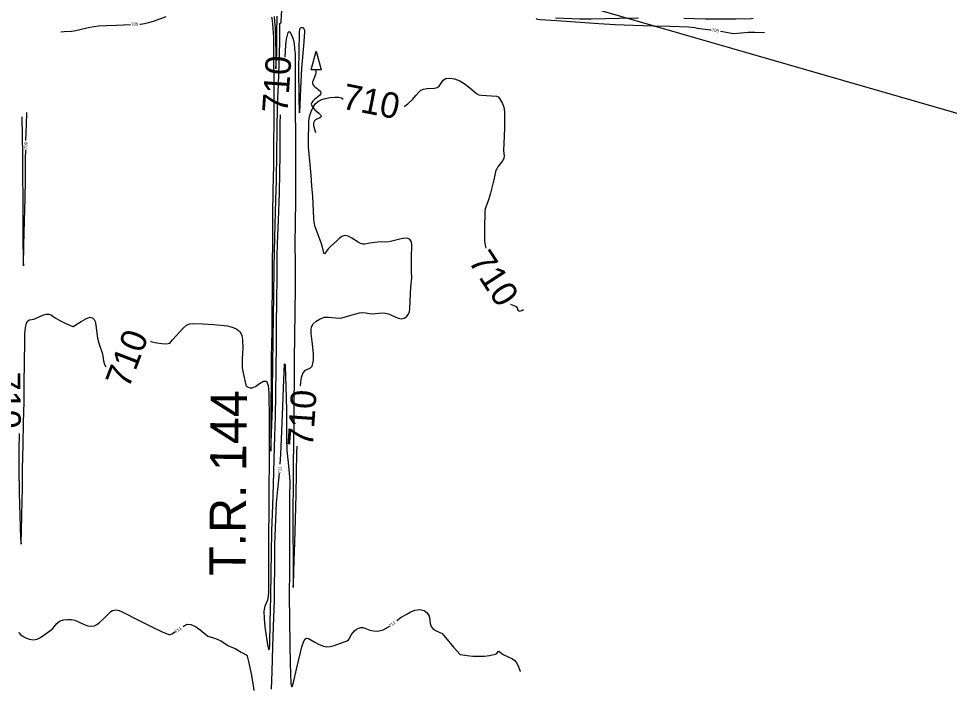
# Model space of a CAD drawing. Extents: x -468548933 to 3387700, y -306089263 to 1207014.
# Drawn here: x 1840205 to 1841407, y 537981 to 538847 of the extents above; entities that cross this region are included whole.
import ezdxf

# ---------------------------------------------------------------- set-up
doc = ezdxf.new("R2010")
doc.units = 0
for name, color, linetype in [('DT_X_Contour_Minor', 7, 'Continuous'), ('Level 19', 7, 'Continuous'), ('Level 40', 7, 'Continuous'), ('Level 56', 7, 'Continuous'), ('SC_Scratch1', 7, 'Continuous')]:
    doc.layers.add(name, color=color, linetype=linetype)

msp = doc.modelspace()

# ---------------------------------------------------------------- linework, layer by layer
at = {"layer": 'DT_X_Contour_Minor'}
for points in [[(1840531.6, 538848.3), (1840532.3, 538844), (1840533.8, 538828.8), (1840533.9, 538822.2), (1840534.2, 538796.9), (1840534.6, 538764.8), (1840534.4, 538739.9), (1840534.4, 538715.2), (1840534.3, 538684.4), (1840533.9, 538656.8), (1840533.4, 538624.7), (1840532.9, 538593), (1840532.7, 538561.2), (1840532.5, 538527.4), (1840532.3, 538498.9), (1840532.1, 538467.3), (1840531.8, 538443.1), (1840531.3, 538408.7), (1840531, 538379.9), (1840530.8, 538347.1), (1840530.6, 538318.7), (1840530.5, 538287.6), (1840530.7, 538287.8), (1840531.4, 538310.8), (1840532.6, 538344.6), (1840533, 538365.7), (1840533.3, 538399.8), (1840533.6, 538431.1), (1840534.1, 538462), (1840534.4, 538489.5), (1840534.8, 538523.6), (1840535.2, 538546.4), (1840536.3, 538580.4), (1840537.3, 538612.4), (1840537.8, 538637.3), (1840538.5, 538673), (1840538.8, 538702.3), (1840539.3, 538733.9), (1840540.4, 538761.8), (1840541.6, 538787.5), (1840542.1, 538816.1), (1840542.5, 538840.4), (1840542.7, 538840.6), (1840543.3, 538840.3), (1840543.6, 538840.7), (1840543.8, 538842.7), (1840544.8, 538857.5)], [(1840361.5, 538839.6), (1840362.4, 538839.6), (1840367.3, 538840.1), (1840373.1, 538841.5), (1840380.5, 538843.9), (1840395.3, 538849.2)], [(1840534.8, 538849.3), (1840535.6, 538843), (1840536.1, 538834.3), (1840537.1, 538802.1), (1840537.2, 538791.4), (1840537.2, 538781.6), (1840537.7, 538788.5), (1840538.2, 538800.9), (1840538.5, 538827.1), (1840538.9, 538849.6)], [(1840873.5, 538847), (1840873.8, 538846.3), (1840875.4, 538845.8), (1840878.2, 538845.4), (1840900, 538844.2), (1840930.5, 538842), (1840954.5, 538840.2), (1840975.5, 538838.8), (1840998.8, 538838), (1841024.8, 538837.3), (1841046.5, 538836.7), (1841070.1, 538835.8), (1841078.6, 538835.1), (1841081.3, 538834.1), (1841098.8, 538832.3), (1841099.6, 538832.2)], [(1841005.7, 538847), (1840981, 538846.6), (1840944.8, 538845.9), (1840929.9, 538846.1), (1840898.3, 538847.1)], [(1841153.8, 538846.6), (1841151.2, 538846.2), (1841131.6, 538846), (1841091.7, 538846), (1841064.1, 538846.6)], [(1840259.2, 538829.7), (1840263.7, 538829.9), (1840273.1, 538830.3), (1840276.6, 538830.8), (1840296.6, 538835.4), (1840307.9, 538837.1), (1840317.9, 538837.7), (1840331.2, 538838.1), (1840349.5, 538839.1)], [(1840549.2, 538796.8), (1840550.2, 538812.7), (1840551, 538819.9), (1840552, 538825.3), (1840553.1, 538828.6), (1840554.3, 538830), (1840555.4, 538829.3), (1840556.5, 538827.5), (1840559.1, 538821.3), (1840559.9, 538818.4), (1840560.6, 538814), (1840561.4, 538808.2), (1840561.9, 538801.1), (1840562.3, 538784.6), (1840562.3, 538762), (1840562.2, 538727.7), (1840562.4, 538696.9), (1840562.7, 538666.4), (1840562.7, 538640.5), (1840562.4, 538611.8), (1840561.9, 538582.4), (1840561.8, 538556.2), (1840562, 538530), (1840562, 538496.5), (1840561.6, 538468.7), (1840561.1, 538435.3), (1840560.9, 538407.4), (1840560.7, 538378.4), (1840560.5, 538353.6), (1840560.2, 538325), (1840559.9, 538298.8), (1840559.6, 538269.1), (1840559.4, 538242), (1840559, 538213.6), (1840559.2, 538185), (1840559.5, 538148.6), (1840559.4, 538117.3), (1840559.5, 538111.8), (1840559.8, 538116.2), (1840560.9, 538146.8), (1840561.5, 538169.6), (1840562.4, 538199.6), (1840563.4, 538231.8), (1840563.9, 538259.3), (1840564.2, 538286.2), (1840564.5, 538294.4)], [(1840567.6, 538828.2), (1840568.2, 538833.2), (1840568.6, 538834.2), (1840569.2, 538834.7), (1840570, 538835), (1840571.2, 538835), (1840572.5, 538834.6), (1840573.5, 538833.6), (1840574, 538831.8), (1840574, 538829), (1840572.9, 538811.6), (1840570.3, 538782.4), (1840569.2, 538755.7), (1840567.5, 538724.9), (1840567.3, 538746.1), (1840566.9, 538780.7), (1840567.2, 538804.3), (1840567.6, 538828.2)], [(1841111.5, 538830.5), (1841116.7, 538829.7), (1841125.8, 538827.6), (1841129.2, 538827.3), (1841147.4, 538829.2), (1841156, 538829.3), (1841168.6, 538828.8)], [(1840703, 538732.9), (1840707.8, 538736.7), (1840713.6, 538742.2), (1840718.6, 538747.6), (1840722, 538751.5), (1840724.6, 538754.1), (1840727.7, 538755.6), (1840732.2, 538756.1), (1840742.1, 538756.7), (1840745.6, 538757.8), (1840748, 538759.5), (1840749.7, 538761.8), (1840751.4, 538764.5), (1840753.5, 538767.2), (1840756.8, 538769.1), (1840761.8, 538769.7), (1840768.1, 538768.9), (1840774.9, 538766.3), (1840781.6, 538762), (1840787.8, 538757.1), (1840796.2, 538749.8), (1840799.2, 538748.3), (1840803, 538747.6), (1840822.4, 538746.5), (1840824.3, 538745.4), (1840825.9, 538743.5), (1840829.8, 538737.1), (1840831.4, 538733.6), (1840832.2, 538730.4), (1840832.5, 538725), (1840832.6, 538706.1), (1840832.3, 538694.6), (1840831.1, 538676.4), (1840832.1, 538669.1), (1840831.9, 538666.1), (1840830.4, 538663.2), (1840823.9, 538655), (1840822.5, 538652.7), (1840821.5, 538650.6), (1840820.7, 538646.5), (1840818.7, 538638.2), (1840814.4, 538621.2), (1840812, 538612.4), (1840807.7, 538600.8), (1840807.2, 538597.7), (1840806.6, 538574.8), (1840806.6, 538563.2), (1840806.8, 538558.5), (1840808, 538551.8), (1840808.3, 538550.1)], [(1840569.1, 538372.3), (1840569.3, 538376.4), (1840570.4, 538383.5), (1840572.5, 538389.1), (1840575.5, 538392.2), (1840582.1, 538395.4), (1840584, 538397.7), (1840585.1, 538400.9), (1840585.6, 538404.7), (1840585.7, 538408.8), (1840585.6, 538413.5), (1840584.4, 538426.2), (1840582.8, 538439.9), (1840582.6, 538444.8), (1840583.3, 538448.6), (1840585.4, 538452.1), (1840589.2, 538455.6), (1840594.2, 538458.7), (1840599.8, 538460.7), (1840605.4, 538461.1), (1840618.9, 538459.7), (1840622.2, 538460.2), (1840632.6, 538462.9), (1840645.3, 538466.4), (1840649.6, 538466.9), (1840653.6, 538466.5), (1840657.6, 538465.7), (1840661.6, 538465.3), (1840665.9, 538465.6), (1840670.3, 538466.2), (1840674.6, 538466.6), (1840678.6, 538466.1), (1840682.6, 538465), (1840695.2, 538459.4), (1840699.4, 538458.8), (1840703.2, 538459.8), (1840706.4, 538462), (1840708.7, 538464.9), (1840709.9, 538468.2), (1840710.4, 538471.6), (1840711.3, 538491.1), (1840711.6, 538499.7), (1840712.8, 538511.9), (1840712.6, 538520.5), (1840712.2, 538529), (1840712.2, 538537.2), (1840712.8, 538554.2), (1840712.3, 538558), (1840710.8, 538560.9), (1840708, 538562.5), (1840704, 538562.9), (1840699.1, 538562.3), (1840683.6, 538558.2), (1840679.9, 538557.8), (1840673, 538558), (1840668.3, 538557.8), (1840658.4, 538556.4), (1840652, 538555.1), (1840649.5, 538555.3), (1840646.6, 538556.2), (1840643.3, 538557.9), (1840635.1, 538563.1), (1840630.5, 538565.4), (1840626.1, 538566.3), (1840622.4, 538565.1), (1840619, 538562.5), (1840615.6, 538559.2), (1840608.2, 538552.8), (1840605.1, 538549.7), (1840600.2, 538542.8), (1840599.3, 538543.7), (1840598.5, 538545.8), (1840597, 538553), (1840595.7, 538557), (1840590.4, 538570.6), (1840588, 538577.7), (1840586.6, 538583.6), (1840586.1, 538588.9), (1840585, 538616.6), (1840583.7, 538630.4), (1840582.6, 538643.7), (1840580.2, 538671.9), (1840579.3, 538679.9), (1840579.3, 538687.5), (1840579.8, 538713.6), (1840580.1, 538717.4), (1840581.1, 538721.3), (1840582.8, 538726.5), (1840585.3, 538732), (1840588.4, 538736.8), (1840592.1, 538740.1), (1840596.4, 538742.1), (1840601.5, 538743.4), (1840607.5, 538744.5), (1840613.5, 538745.1), (1840618.5, 538745.1), (1840621.8, 538744.1), (1840624.2, 538742.7)], [(1840214.2, 538689.1), (1840214.9, 538709.9), (1840215.3, 538725.5)], [(1840375.3, 538429.7), (1840377.1, 538429), (1840383.5, 538427.6), (1840389.9, 538426.8), (1840395.1, 538426.5), (1840398.2, 538426.7), (1840400, 538427.4), (1840404, 538431.9), (1840416.8, 538446.1), (1840421.6, 538450.4), (1840424.6, 538452), (1840425.9, 538452.3), (1840430.9, 538452.5), (1840442.6, 538452.1), (1840457, 538451.3), (1840474.5, 538449.6), (1840477.6, 538448.9), (1840482, 538447.6), (1840486.9, 538445.3), (1840490.9, 538441.9), (1840493.2, 538437.2), (1840494, 538432), (1840494.3, 538420.7), (1840493.8, 538407), (1840493.6, 538398.5), (1840493.8, 538395.3), (1840495.3, 538387), (1840498.2, 538372.9), (1840498.8, 538372.2), (1840499.7, 538371.5), (1840501.2, 538370.6), (1840503.4, 538369.8), (1840506.6, 538369.6), (1840510.8, 538371.3), (1840515.9, 538375), (1840521.1, 538378.3), (1840525.2, 538378.3), (1840527.4, 538372.8), (1840528.2, 538363.1), (1840528.4, 538329.6), (1840528.4, 538302.7), (1840528.4, 538272), (1840528.2, 538241.5), (1840527.9, 538210.6), (1840527.7, 538178.6), (1840527.7, 538148.6), (1840527.8, 538121.6), (1840527.7, 538105.5), (1840527.3, 538099.8), (1840526.3, 538095.4), (1840522.7, 538087.5), (1840521.7, 538081), (1840522, 538071.4), (1840523.1, 538060.8), (1840526.4, 538037.5), (1840527.8, 538032.1), (1840528.5, 538031.1), (1840529, 538032.9), (1840529.3, 538037.7), (1840530, 538067.4), (1840530.8, 538099.6), (1840531.3, 538131.1), (1840531.5, 538155.5), (1840532, 538184.9), (1840533.1, 538217.7), (1840534.1, 538244.5), (1840535, 538277.9), (1840535.7, 538306.6), (1840536.5, 538332.6), (1840537.1, 538360.7), (1840537.5, 538394.5), (1840537.8, 538423.3), (1840538.1, 538449.1), (1840538.5, 538484.1), (1840538.7, 538510.8), (1840538.9, 538539.2), (1840539.3, 538556.3), (1840540.4, 538586.2), (1840541.7, 538621.5), (1840542.4, 538647.5), (1840542.6, 538671.1), (1840542.9, 538711.1), (1840543.2, 538722.5)], [(1840208.9, 538719.5), (1840209, 538717.9), (1840209.4, 538696.2), (1840209.7, 538670), (1840209.9, 538643.5), (1840210.3, 538614.2), (1840210.3, 538584.4), (1840210.3, 538565.3), (1840210.7, 538532.8), (1840210.9, 538527.2), (1840211.7, 538554.1), (1840212.4, 538584.9), (1840213.2, 538615), (1840213.6, 538637.9), (1840213.8, 538665.4), (1840214, 538677.1)], [(1840840.2, 538477.6), (1840846.6, 538475), (1840848.1, 538474.1), (1840848.8, 538472.8), (1840849.4, 538471), (1840850.3, 538469.3), (1840852, 538468.6), (1840854.8, 538469.6), (1840857.1, 538470.8)], [(1840205.3, 538310.5), (1840205.1, 538290), (1840204.9, 538266), (1840205.4, 538233.6), (1840206.2, 538204.4), (1840207.1, 538174.9), (1840207.9, 538167.5), (1840208.2, 538169.5), (1840208.7, 538185.2), (1840209.1, 538205.6), (1840209.7, 538240.3), (1840210, 538264.6), (1840210.6, 538296.3), (1840211.3, 538324.7), (1840211.9, 538351.7), (1840212, 538375.5), (1840212.3, 538402), (1840212.7, 538429.8), (1840213, 538439.2), (1840213.6, 538447.2), (1840214.8, 538453.1), (1840216.7, 538456.3), (1840218.9, 538457.5), (1840224.6, 538458.3), (1840231.3, 538461.3), (1840235.9, 538463.3), (1840240.4, 538464.6), (1840244.2, 538464.6), (1840247.2, 538463.5), (1840252.2, 538460.2), (1840258.1, 538456.5), (1840266, 538452.5), (1840274.8, 538448.7), (1840275.3, 538448.7), (1840277.6, 538450.1), (1840285.8, 538455.5), (1840291.7, 538458.8), (1840296.9, 538460.7), (1840300.4, 538460.2), (1840302.5, 538457.9), (1840303.5, 538455.3), (1840304.5, 538450.7), (1840306.9, 538433.9), (1840308.3, 538427.2), (1840310.5, 538421), (1840311.9, 538417.4), (1840313, 538413.4), (1840314.5, 538404.5), (1840315.9, 538399.8), (1840317.4, 538396.8)], [(1840542.7, 538271.1), (1840543.5, 538283.8), (1840545, 538313.7), (1840546, 538345.5), (1840547, 538369.4), (1840548.5, 538400.2), (1840548.7, 538400.5), (1840549, 538399.3), (1840549.2, 538397.2), (1840550, 538371.6), (1840551.1, 538340.1), (1840550.9, 538319.4), (1840550.7, 538303.7), (1840551.4, 538288.7), (1840552.9, 538273.1), (1840554.8, 538254.5), (1840555, 538248.3), (1840554.9, 538228.8), (1840554.9, 538191.8), (1840554.8, 538165.1), (1840554.7, 538134.1), (1840554.5, 538101.3), (1840554.8, 538069.9), (1840555.3, 538037.8), (1840555.8, 538013.4), (1840556.7, 537987.6), (1840557.2, 537983.7), (1840557.7, 537983.3), (1840558.5, 537984.4), (1840560, 537988.9), (1840564, 538006.3), (1840568.9, 538027.8), (1840570.9, 538035), (1840572.9, 538040.9), (1840574.8, 538044.9), (1840576.8, 538046.3), (1840579.2, 538045.7), (1840587.5, 538040.8), (1840593.1, 538038), (1840598.5, 538035.9), (1840603.1, 538035), (1840607.2, 538035.3), (1840611.2, 538036.3), (1840626.9, 538041.9), (1840629.3, 538042.8), (1840631, 538044), (1840632.3, 538045.7), (1840634.6, 538050.3), (1840636.5, 538053), (1840638.8, 538055.5), (1840641.4, 538057.7), (1840644.2, 538059.2), (1840647, 538060), (1840649.6, 538060), (1840652.1, 538059.3), (1840658.5, 538056.7), (1840663.3, 538055.6), (1840669.1, 538055.4), (1840675.7, 538057), (1840682.6, 538060.7), (1840684, 538061.7)], [(1840531.4, 537980.3), (1840532.3, 538003), (1840533.4, 538035.1), (1840534.2, 538061.2), (1840535.3, 538095.3), (1840535.6, 538108.8), (1840535.7, 538141.6), (1840535.9, 538167.1), (1840537.1, 538199.4), (1840538.1, 538220.9), (1840539.8, 538238.1), (1840541.7, 538259.1)], [(1840204.6, 538053.7), (1840205.5, 538053), (1840206.8, 538051.5), (1840209.3, 538049.4), (1840213.4, 538046.9), (1840218.6, 538044.8), (1840223.9, 538043.9), (1840228.7, 538044.8), (1840233.1, 538047), (1840245.3, 538055.6), (1840248.8, 538058.7), (1840254.3, 538065.3), (1840257.8, 538068), (1840262.6, 538069.7), (1840268, 538070.5), (1840273.2, 538070.4), (1840277.5, 538069.4), (1840281.2, 538067.8), (1840289.6, 538063.9), (1840294.3, 538062.3), (1840298.8, 538061.6), (1840302.7, 538062.2), (1840306, 538063.9), (1840309.1, 538066.3), (1840314.8, 538071.7), (1840324.1, 538080.8), (1840325.9, 538081.8), (1840328.2, 538082.5), (1840331.1, 538082.7), (1840334.6, 538082), (1840338.7, 538080.3), (1840359.8, 538069.4), (1840375, 538061.5), (1840390.2, 538054.5), (1840398.7, 538050.9), (1840400.5, 538050.8), (1840402.6, 538051.8), (1840407.3, 538054.6)], [(1840693.5, 538068.9), (1840699, 538073.3), (1840705.5, 538076.9), (1840710.6, 538079.6), (1840716.9, 538082.2), (1840723.3, 538083.3), (1840728.7, 538082.1), (1840732.8, 538078.9), (1840735.2, 538074.5), (1840736.1, 538069.8), (1840736.5, 538065.2), (1840737.7, 538061.1), (1840740.6, 538058), (1840744.3, 538055.7), (1840752, 538052), (1840754, 538049.6), (1840766.7, 538034.6), (1840775.2, 538025), (1840784.5, 538023.8), (1840791.6, 538023.1), (1840799.4, 538022.8), (1840806.8, 538023.1), (1840813.3, 538023.9), (1840821.1, 538025.5), (1840822.5, 538026.3), (1840824.5, 538029), (1840825.3, 538029.2), (1840830.9, 538025.1), (1840843, 538019.4), (1840846, 538017.2), (1840848.1, 538014.5), (1840849.6, 538011.5), (1840852.8, 538003.5), (1840853, 538003.2)], [(1840417.3, 538061.3), (1840418.6, 538062.2), (1840422.6, 538064.1), (1840427.3, 538063.9), (1840433.3, 538061.1), (1840439.4, 538056.9), (1840449.4, 538048.9), (1840456.7, 538046.5), (1840461.5, 538044.8), (1840466, 538042.7), (1840469.7, 538040.5), (1840475.3, 538036.8), (1840481.1, 538034.2), (1840484.6, 538032.7), (1840492.4, 538028.3), (1840499.5, 538024.1), (1840500, 538022.9), (1840502.2, 538014.5), (1840505.4, 538000.3), (1840507.6, 537987.6), (1840508.9, 537978.5)]]:
    msp.add_lwpolyline(points, dxfattribs=at)
at = {"layer": 'Level 56'}
for p, q in [((1840582.6, 538780.4), (1840589.3, 538804.4)), ((1840589.3, 538804.4), (1840595.5, 538780.4)), ((1840595.5, 538780.4), (1840582.6, 538780.4))]:
    msp.add_line(p, q, dxfattribs=at)
msp.add_spline([(1840589, 538780.4), (1840589, 538779.5), (1840586.7, 538769.6), (1840584.5, 538763.4), (1840595.4, 538750.6), (1840582.9, 538736.1), (1840595.2, 538719.2), (1840588.5, 538715.9), (1840588.5, 538699.4)], degree=3, dxfattribs=at)
at = {"layer": 'SC_Scratch1'}
msp.add_lwpolyline([(1834448.4, 536360.5), (1835055.8, 534489.4), (1836664.2, 534206.2), (1839225.8, 534394.2), (1842361.7, 536308.3), (1842189.4, 536805.1), (1841581.8, 538676.6), (1840313.7, 539042.5), (1837357.7, 538260.2), (1834781, 538194.3), (1834403.1, 536496.4)], close=True, dxfattribs=at)

# ---------------------------------------------------------------- texts
at = {"layer": 'Level 19'}
for s, height, rotation, p in [('709', 4, 1.9538, (1840350.3, 538837.2)), ('709', 4, 351.6872, (1841100.1, 538830.1)), ('710', 33, 85.9666, (1840552.2, 538723.9)), ('710', 33, 348.8052, (1840621.1, 538730.7)), ('709', 4, 89.158, (1840216, 538677.9)), ('710', 33, 303.0163, (1840785, 538533.3)), ('710', 33, 69.1159, (1840346.9, 538367.5)), ('710', 33, 270.5793, (1840174, 538390.2)), ('710', 33, 86.1098, (1840584.9, 538292.4)), ('711', 4, 86.001, (1840543.8, 538258.8)), ('711', 4, 35.1624, (1840408.5, 538052.7)), ('711', 4, 35.913, (1840685, 538060))]:
    msp.add_text(s, height=height, rotation=rotation, dxfattribs=at).set_placement(p)
at = {"layer": 'Level 40'}
msp.add_text('T.R. 144', height=46.8, rotation=89.5262, dxfattribs=at).set_placement((1840497.8, 538126.3))

doc.saveas('drawing.dxf')
